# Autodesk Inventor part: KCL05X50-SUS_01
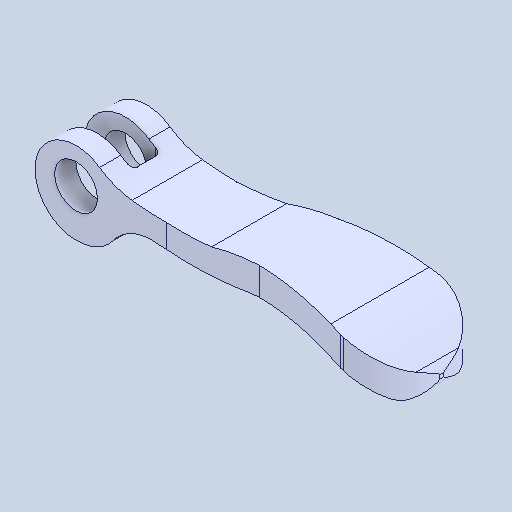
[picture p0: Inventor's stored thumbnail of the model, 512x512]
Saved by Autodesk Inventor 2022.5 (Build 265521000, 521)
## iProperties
Created: 2024-08
Part Number: KCL05X50-SUS_01
Material: 一般
Document SubType Name: Modeling
Designer: ImaoCorp
Density: 1 g/cm^3
Appearance: 既定
Author: ImaoCorp
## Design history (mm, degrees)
feature "KCL05X50-SUS_01"
node "ソリッド1"
